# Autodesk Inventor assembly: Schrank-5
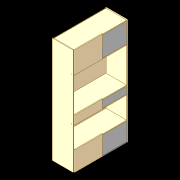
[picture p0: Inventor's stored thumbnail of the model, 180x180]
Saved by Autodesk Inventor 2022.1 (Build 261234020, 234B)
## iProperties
Created: 2022-03
Part Number: Schrank-5
Document SubType Name: Assembly
Designer: Ruhl
Author: Ruhl
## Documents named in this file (2)
- Z:\INVENTOR\FORUM UND TEST\VOLUMENKÖRPER VERSCHMELZEN\Schrank-5.iam
- Z:\INVENTOR\FORUM UND TEST\VOLUMENKÖRPER VERSCHMELZEN\Korpus-5.ipt
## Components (1 placed, 1 different names)
1. Korpus-5:1
